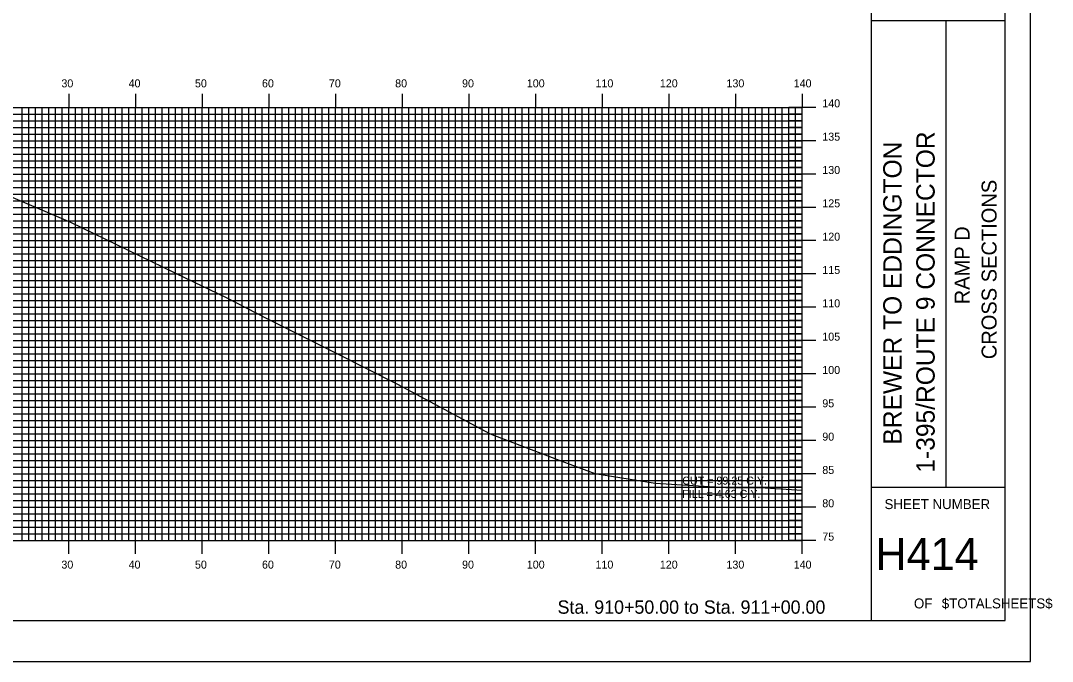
# Model space of a CAD drawing. Extents: x 859471 to 859814, y 364765 to 364985.
# Drawn here: x 859659.7 to 859814.4, y 364765.2 to 364861.3 of the extents above; entities that cross this region are included whole.
import ezdxf

# ---------------------------------------------------------------- set-up
doc = ezdxf.new("R2010")
doc.units = 0
for name, color, linetype in [('BORDER', 7, 'Continuous'), ('D_Text_Standard', 7, 'Continuous'), ('H_V ANNOTATION', 7, 'Continuous'), ('MAJOR', 7, 'Continuous'), ('MINOR', 7, 'Continuous'), ('PLOT BOUNDARY', 7, 'Continuous'), ('S_Roadway_Centerline', 7, 'Continuous')]:
    doc.layers.add(name, color=color, linetype=linetype)

msp = doc.modelspace()

# ---------------------------------------------------------------- linework, layer by layer
at = {"layer": 'BORDER'}
for p, q in [((859787.27, 364771.3), (859787.27, 364981.3)), ((859787.27, 364861.31), (859807.27, 364861.31)), ((859798.46, 364791.31), (859798.46, 364861.31)), ((859787.27, 364791.31), (859807.27, 364791.31))]:
    msp.add_line(p, q, dxfattribs=at)
msp.add_lwpolyline([(859487.27, 364771.3), (859807.27, 364771.3), (859807.27, 364981.3), (859487.27, 364981.3)], close=True, dxfattribs=at)
at = {"layer": 'MAJOR'}
for p, q in [((859666.87, 364850.31), (859666.87, 364848.3)), ((859676.87, 364850.31), (859676.87, 364848.3)), ((859686.87, 364850.31), (859686.87, 364848.3)), ((859696.87, 364850.31), (859696.87, 364848.3)), ((859706.87, 364850.31), (859706.87, 364848.3)), ((859716.87, 364850.31), (859716.87, 364848.3)), ((859726.87, 364850.31), (859726.87, 364848.3)), ((859736.87, 364850.31), (859736.87, 364848.3)), ((859746.87, 364850.31), (859746.87, 364848.3)), ((859756.87, 364850.31), (859756.87, 364848.3)), ((859766.87, 364850.31), (859766.87, 364848.3)), ((859776.87, 364850.31), (859776.87, 364848.3)), ((859496.87, 364848.3), (859776.87, 364848.3)), ((859496.87, 364848.3), (859776.87, 364848.3)), ((859666.87, 364783.3), (859666.87, 364848.3)), ((859676.87, 364783.3), (859676.87, 364848.3)), ((859686.87, 364783.3), (859686.87, 364848.3)), ((859696.87, 364783.3), (859696.87, 364848.3)), ((859706.87, 364783.3), (859706.87, 364848.3)), ((859716.87, 364783.3), (859716.87, 364848.3)), ((859726.87, 364783.3), (859726.87, 364848.3)), ((859736.87, 364783.3), (859736.87, 364848.3)), ((859746.87, 364783.3), (859746.87, 364848.3)), ((859756.87, 364783.3), (859756.87, 364848.3)), ((859766.87, 364783.3), (859766.87, 364848.3)), ((859778.88, 364848.3), (859774.87, 364848.3)), ((859776.87, 364783.3), (859776.87, 364848.3)), ((859776.87, 364783.3), (859776.87, 364848.3)), ((859496.87, 364843.3), (859776.87, 364843.3)), ((859778.88, 364843.3), (859774.87, 364843.3)), ((859496.87, 364838.3), (859776.87, 364838.3)), ((859778.88, 364838.3), (859774.87, 364838.3)), ((859496.87, 364833.3), (859776.87, 364833.3)), ((859778.88, 364833.3), (859774.87, 364833.3)), ((859496.87, 364828.3), (859776.87, 364828.3)), ((859778.88, 364828.3), (859774.87, 364828.3)), ((859496.87, 364823.3), (859776.87, 364823.3)), ((859778.88, 364823.3), (859774.87, 364823.3)), ((859496.87, 364818.3), (859776.87, 364818.3)), ((859778.88, 364818.3), (859774.87, 364818.3)), ((859496.87, 364813.3), (859776.87, 364813.3)), ((859778.88, 364813.3), (859774.87, 364813.3)), ((859496.87, 364808.3), (859776.87, 364808.3)), ((859778.88, 364808.3), (859774.87, 364808.3)), ((859496.87, 364803.3), (859776.87, 364803.3)), ((859778.88, 364803.3), (859774.87, 364803.3)), ((859496.87, 364798.3), (859776.87, 364798.3)), ((859778.88, 364798.3), (859774.87, 364798.3)), ((859496.87, 364793.3), (859776.87, 364793.3)), ((859778.88, 364793.3), (859774.87, 364793.3)), ((859496.87, 364788.3), (859776.87, 364788.3)), ((859778.88, 364788.3), (859774.87, 364788.3)), ((859496.87, 364783.3), (859776.87, 364783.3)), ((859496.87, 364783.3), (859776.87, 364783.3)), ((859666.87, 364781.3), (859666.87, 364783.3)), ((859676.87, 364781.3), (859676.87, 364783.3)), ((859686.87, 364781.3), (859686.87, 364783.3)), ((859696.87, 364781.3), (859696.87, 364783.3)), ((859706.87, 364781.3), (859706.87, 364783.3)), ((859716.87, 364781.3), (859716.87, 364783.3)), ((859726.87, 364781.3), (859726.87, 364783.3)), ((859736.87, 364781.3), (859736.87, 364783.3)), ((859746.87, 364781.3), (859746.87, 364783.3)), ((859756.87, 364781.3), (859756.87, 364783.3)), ((859766.87, 364781.3), (859766.87, 364783.3)), ((859778.88, 364783.3), (859774.87, 364783.3)), ((859776.87, 364781.3), (859776.87, 364783.3))]:
    msp.add_line(p, q, dxfattribs=at)
at = {"layer": 'MINOR'}
for p, q in [((859496.87, 364847.3), (859776.87, 364847.3)), ((859659.87, 364783.3), (859659.87, 364848.3)), ((859660.87, 364783.3), (859660.87, 364848.3)), ((859661.87, 364783.3), (859661.87, 364848.3)), ((859662.87, 364783.3), (859662.87, 364848.3)), ((859663.87, 364783.3), (859663.87, 364848.3)), ((859664.87, 364783.3), (859664.87, 364848.3)), ((859665.87, 364783.3), (859665.87, 364848.3)), ((859667.87, 364783.3), (859667.87, 364848.3)), ((859668.87, 364783.3), (859668.87, 364848.3)), ((859669.87, 364783.3), (859669.87, 364848.3)), ((859670.87, 364783.3), (859670.87, 364848.3)), ((859671.87, 364783.3), (859671.87, 364848.3)), ((859672.87, 364783.3), (859672.87, 364848.3)), ((859673.87, 364783.3), (859673.87, 364848.3)), ((859674.87, 364783.3), (859674.87, 364848.3)), ((859675.87, 364783.3), (859675.87, 364848.3)), ((859677.87, 364783.3), (859677.87, 364848.3)), ((859678.87, 364783.3), (859678.87, 364848.3)), ((859679.87, 364783.3), (859679.87, 364848.3)), ((859680.87, 364783.3), (859680.87, 364848.3)), ((859681.87, 364783.3), (859681.87, 364848.3)), ((859682.87, 364783.3), (859682.87, 364848.3)), ((859683.87, 364783.3), (859683.87, 364848.3)), ((859684.87, 364783.3), (859684.87, 364848.3)), ((859685.87, 364783.3), (859685.87, 364848.3)), ((859687.87, 364783.3), (859687.87, 364848.3)), ((859688.87, 364783.3), (859688.87, 364848.3)), ((859689.87, 364783.3), (859689.87, 364848.3)), ((859690.87, 364783.3), (859690.87, 364848.3)), ((859691.87, 364783.3), (859691.87, 364848.3)), ((859692.87, 364783.3), (859692.87, 364848.3)), ((859693.87, 364783.3), (859693.87, 364848.3)), ((859694.87, 364783.3), (859694.87, 364848.3)), ((859695.87, 364783.3), (859695.87, 364848.3)), ((859697.87, 364783.3), (859697.87, 364848.3)), ((859698.87, 364783.3), (859698.87, 364848.3)), ((859699.87, 364783.3), (859699.87, 364848.3)), ((859700.87, 364783.3), (859700.87, 364848.3)), ((859701.87, 364783.3), (859701.87, 364848.3)), ((859702.87, 364783.3), (859702.87, 364848.3)), ((859703.87, 364783.3), (859703.87, 364848.3)), ((859704.87, 364783.3), (859704.87, 364848.3)), ((859705.87, 364783.3), (859705.87, 364848.3)), ((859707.87, 364783.3), (859707.87, 364848.3)), ((859708.87, 364783.3), (859708.87, 364848.3)), ((859709.87, 364783.3), (859709.87, 364848.3)), ((859710.87, 364783.3), (859710.87, 364848.3)), ((859711.87, 364783.3), (859711.87, 364848.3)), ((859712.87, 364783.3), (859712.87, 364848.3)), ((859713.87, 364783.3), (859713.87, 364848.3)), ((859714.87, 364783.3), (859714.87, 364848.3)), ((859715.87, 364783.3), (859715.87, 364848.3)), ((859717.87, 364783.3), (859717.87, 364848.3)), ((859718.87, 364783.3), (859718.87, 364848.3)), ((859719.87, 364783.3), (859719.87, 364848.3)), ((859720.87, 364783.3), (859720.87, 364848.3)), ((859721.87, 364783.3), (859721.87, 364848.3)), ((859722.87, 364783.3), (859722.87, 364848.3)), ((859723.87, 364783.3), (859723.87, 364848.3)), ((859724.87, 364783.3), (859724.87, 364848.3)), ((859725.87, 364783.3), (859725.87, 364848.3)), ((859727.87, 364783.3), (859727.87, 364848.3)), ((859728.87, 364783.3), (859728.87, 364848.3)), ((859729.87, 364783.3), (859729.87, 364848.3)), ((859730.87, 364783.3), (859730.87, 364848.3)), ((859731.87, 364783.3), (859731.87, 364848.3)), ((859732.87, 364783.3), (859732.87, 364848.3)), ((859733.87, 364783.3), (859733.87, 364848.3)), ((859734.87, 364783.3), (859734.87, 364848.3)), ((859735.87, 364783.3), (859735.87, 364848.3)), ((859737.87, 364783.3), (859737.87, 364848.3)), ((859738.87, 364783.3), (859738.87, 364848.3)), ((859739.87, 364783.3), (859739.87, 364848.3)), ((859740.87, 364783.3), (859740.87, 364848.3)), ((859741.87, 364783.3), (859741.87, 364848.3)), ((859742.87, 364783.3), (859742.87, 364848.3)), ((859743.87, 364783.3), (859743.87, 364848.3)), ((859744.87, 364783.3), (859744.87, 364848.3)), ((859745.87, 364783.3), (859745.87, 364848.3)), ((859747.87, 364783.3), (859747.87, 364848.3)), ((859748.87, 364783.3), (859748.87, 364848.3)), ((859749.87, 364783.3), (859749.87, 364848.3)), ((859750.87, 364783.3), (859750.87, 364848.3)), ((859751.87, 364783.3), (859751.87, 364848.3)), ((859752.87, 364783.3), (859752.87, 364848.3)), ((859753.87, 364783.3), (859753.87, 364848.3)), ((859754.87, 364783.3), (859754.87, 364848.3)), ((859755.87, 364783.3), (859755.87, 364848.3)), ((859757.87, 364783.3), (859757.87, 364848.3)), ((859758.87, 364783.3), (859758.87, 364848.3)), ((859759.87, 364783.3), (859759.87, 364848.3)), ((859760.87, 364783.3), (859760.87, 364848.3)), ((859761.87, 364783.3), (859761.87, 364848.3)), ((859762.87, 364783.3), (859762.87, 364848.3)), ((859763.87, 364783.3), (859763.87, 364848.3)), ((859764.87, 364783.3), (859764.87, 364848.3)), ((859765.87, 364783.3), (859765.87, 364848.3)), ((859767.87, 364783.3), (859767.87, 364848.3)), ((859768.87, 364783.3), (859768.87, 364848.3)), ((859769.87, 364783.3), (859769.87, 364848.3)), ((859770.87, 364783.3), (859770.87, 364848.3)), ((859771.87, 364783.3), (859771.87, 364848.3)), ((859772.87, 364783.3), (859772.87, 364848.3)), ((859773.87, 364783.3), (859773.87, 364848.3)), ((859774.87, 364783.3), (859774.87, 364848.3)), ((859776.87, 364847.3), (859774.87, 364847.3)), ((859775.87, 364783.3), (859775.87, 364848.3)), ((859496.87, 364846.3), (859776.87, 364846.3)), ((859776.87, 364846.3), (859774.87, 364846.3)), ((859496.87, 364845.3), (859776.87, 364845.3)), ((859496.87, 364844.3), (859776.87, 364844.3)), ((859776.87, 364845.3), (859774.87, 364845.3)), ((859776.87, 364844.3), (859774.87, 364844.3)), ((859496.87, 364842.3), (859776.87, 364842.3)), ((859496.87, 364841.3), (859776.87, 364841.3)), ((859776.87, 364842.3), (859774.87, 364842.3)), ((859776.87, 364841.3), (859774.87, 364841.3)), ((859496.87, 364840.3), (859776.87, 364840.3)), ((859776.87, 364840.3), (859774.87, 364840.3)), ((859496.87, 364839.3), (859776.87, 364839.3)), ((859776.87, 364839.3), (859774.87, 364839.3)), ((859496.87, 364837.3), (859776.87, 364837.3)), ((859776.87, 364837.3), (859774.87, 364837.3)), ((859496.87, 364836.3), (859776.87, 364836.3)), ((859496.87, 364835.3), (859776.87, 364835.3)), ((859776.87, 364836.3), (859774.87, 364836.3)), ((859776.87, 364835.3), (859774.87, 364835.3)), ((859496.87, 364834.3), (859776.87, 364834.3)), ((859776.87, 364834.3), (859774.87, 364834.3)), ((859496.87, 364832.3), (859776.87, 364832.3)), ((859776.87, 364832.3), (859774.87, 364832.3)), ((859496.87, 364831.3), (859776.87, 364831.3)), ((859496.87, 364830.3), (859776.87, 364830.3)), ((859776.87, 364831.3), (859774.87, 364831.3)), ((859776.87, 364830.3), (859774.87, 364830.3)), ((859496.87, 364829.3), (859776.87, 364829.3)), ((859776.87, 364829.3), (859774.87, 364829.3)), ((859496.87, 364827.3), (859776.87, 364827.3)), ((859776.87, 364827.3), (859774.87, 364827.3)), ((859496.87, 364826.3), (859776.87, 364826.3)), ((859776.87, 364826.3), (859774.87, 364826.3)), ((859496.87, 364825.3), (859776.87, 364825.3)), ((859496.87, 364824.3), (859776.87, 364824.3)), ((859776.87, 364825.3), (859774.87, 364825.3)), ((859776.87, 364824.3), (859774.87, 364824.3)), ((859496.87, 364822.3), (859776.87, 364822.3)), ((859496.87, 364821.3), (859776.87, 364821.3)), ((859776.87, 364822.3), (859774.87, 364822.3)), ((859776.87, 364821.3), (859774.87, 364821.3)), ((859496.87, 364820.3), (859776.87, 364820.3)), ((859776.87, 364820.3), (859774.87, 364820.3)), ((859496.87, 364819.3), (859776.87, 364819.3)), ((859776.87, 364819.3), (859774.87, 364819.3)), ((859496.87, 364817.3), (859776.87, 364817.3)), ((859496.87, 364816.3), (859776.87, 364816.3)), ((859776.87, 364817.3), (859774.87, 364817.3)), ((859776.87, 364816.3), (859774.87, 364816.3)), ((859496.87, 364815.3), (859776.87, 364815.3)), ((859776.87, 364815.3), (859774.87, 364815.3)), ((859496.87, 364814.3), (859776.87, 364814.3)), ((859776.87, 364814.3), (859774.87, 364814.3)), ((859496.87, 364812.3), (859776.87, 364812.3)), ((859776.87, 364812.3), (859774.87, 364812.3)), ((859496.87, 364811.3), (859776.87, 364811.3)), ((859496.87, 364810.3), (859776.87, 364810.3)), ((859776.87, 364811.3), (859774.87, 364811.3)), ((859776.87, 364810.3), (859774.87, 364810.3)), ((859496.87, 364809.3), (859776.87, 364809.3)), ((859776.87, 364809.3), (859774.87, 364809.3)), ((859496.87, 364807.3), (859776.87, 364807.3)), ((859776.87, 364807.3), (859774.87, 364807.3)), ((859496.87, 364806.3), (859776.87, 364806.3)), ((859776.87, 364806.3), (859774.87, 364806.3)), ((859496.87, 364805.3), (859776.87, 364805.3)), ((859496.87, 364804.3), (859776.87, 364804.3)), ((859776.87, 364805.3), (859774.87, 364805.3)), ((859776.87, 364804.3), (859774.87, 364804.3)), ((859496.87, 364802.3), (859776.87, 364802.3)), ((859496.87, 364801.3), (859776.87, 364801.3)), ((859776.87, 364802.3), (859774.87, 364802.3)), ((859776.87, 364801.3), (859774.87, 364801.3)), ((859496.87, 364800.3), (859776.87, 364800.3)), ((859496.87, 364799.3), (859776.87, 364799.3)), ((859776.87, 364800.3), (859774.87, 364800.3)), ((859776.87, 364799.3), (859774.87, 364799.3)), ((859496.87, 364797.3), (859776.87, 364797.3)), ((859496.87, 364796.3), (859776.87, 364796.3)), ((859776.87, 364797.3), (859774.87, 364797.3)), ((859776.87, 364796.3), (859774.87, 364796.3)), ((859496.87, 364795.3), (859776.87, 364795.3)), ((859776.87, 364795.3), (859774.87, 364795.3)), ((859496.87, 364794.3), (859776.87, 364794.3)), ((859776.87, 364794.3), (859774.87, 364794.3)), ((859496.87, 364792.3), (859776.87, 364792.3)), ((859776.87, 364792.3), (859774.87, 364792.3)), ((859496.87, 364791.3), (859776.87, 364791.3)), ((859496.87, 364790.3), (859776.87, 364790.3)), ((859776.87, 364791.3), (859774.87, 364791.3)), ((859776.87, 364790.3), (859774.87, 364790.3)), ((859496.87, 364789.3), (859776.87, 364789.3)), ((859776.87, 364789.3), (859774.87, 364789.3)), ((859496.87, 364787.3), (859776.87, 364787.3)), ((859776.87, 364787.3), (859774.87, 364787.3)), ((859496.87, 364786.3), (859776.87, 364786.3)), ((859496.87, 364785.3), (859776.87, 364785.3)), ((859776.87, 364786.3), (859774.87, 364786.3)), ((859776.87, 364785.3), (859774.87, 364785.3)), ((859496.87, 364784.3), (859776.87, 364784.3)), ((859776.87, 364784.3), (859774.87, 364784.3))]:
    msp.add_line(p, q, dxfattribs=at)
at = {"layer": 'PLOT BOUNDARY'}
msp.add_lwpolyline([(859471.09, 364765.18), (859811.09, 364765.18), (859811.09, 364985.18), (859471.09, 364985.18)], close=True, dxfattribs=at)
at = {"layer": 'S_Roadway_Centerline'}
msp.add_lwpolyline([(859658.14, 364834.91), (859667.12, 364831.06), (859684.44, 364822.68), (859690.37, 364819.81), (859696.68, 364816.55), (859706.98, 364811.41), (859716.16, 364806.75), (859730.06, 364799.32), (859740.03, 364795.52), (859745.77, 364793.38), (859754.79, 364791.9), (859765.39, 364791.27), (859771.29, 364791.21), (859776.87, 364790.87)], dxfattribs=at)

# ---------------------------------------------------------------- texts
at = {"layer": 'BORDER'}
for s, height, p in [('1-395/ROUTE 9 CONNECTOR', 2.7557, (859796.72, 364793.5)), ('BREWER TO EDDINGTON', 2.7557, (859791.76, 364797.71)), ('CROSS SECTIONS', 2.25, (859806.01, 364810.52)), ('RAMP D', 2.25, (859801.96, 364818.75))]:
    msp.add_text(s, height=height, rotation=90, dxfattribs=at).set_placement(p)
for s, height, p in [('SHEET NUMBER', 1.4905, (859789.2, 364788.03)), ('H414', 4.839, (859787.85, 364778.87)), ('OF', 1.491, (859793.61, 364773.13)), ('$TOTALSHEETS$', 1.4905, (859797.79, 364773.13))]:
    msp.add_text(s, height=height, dxfattribs=at).set_placement(p)
at = {"layer": 'D_Text_Standard'}
for s, p in [('CUT = 99.25 C.Y.', (859758.87, 364791.7)), ('FILL = 4.63 C.Y.', (859758.87, 364789.71))]:
    msp.add_text(s, height=1.2, dxfattribs=at).set_placement(p)
at = {"layer": 'H_V ANNOTATION'}
for s, height, p in [('30', 1.2, (859665.77, 364851.3)), ('40', 1.2, (859675.85, 364851.3)), ('50', 1.2, (859685.8, 364851.3)), ('60', 1.2, (859695.85, 364851.3)), ('70', 1.2, (859705.88, 364851.3)), ('80', 1.2, (859715.82, 364851.3)), ('90', 1.2, (859725.85, 364851.3)), ('100', 1.2, (859735.56, 364851.3)), ('110', 1.2, (859745.86, 364851.3)), ('120', 1.2, (859755.51, 364851.3)), ('130', 1.2, (859765.5, 364851.3)), ('140', 1.2, (859775.58, 364851.3)), ('140', 1.2, (859779.87, 364848.3)), ('135', 1.2, (859779.87, 364843.3)), ('130', 1.2, (859779.87, 364838.3)), ('125', 1.2, (859779.87, 364833.3)), ('120', 1.2, (859779.87, 364828.3)), ('115', 1.2, (859779.87, 364823.3)), ('110', 1.2, (859779.87, 364818.3)), ('105', 1.2, (859779.87, 364813.3)), ('100', 1.2, (859779.87, 364808.3)), ('95', 1.2, (859779.87, 364803.3)), ('90', 1.2, (859779.87, 364798.3)), ('85', 1.2, (859779.87, 364793.3)), ('80', 1.2, (859779.87, 364788.3)), ('75', 1.2, (859779.87, 364783.3)), ('30', 1.2, (859665.77, 364779.1)), ('40', 1.2, (859675.85, 364779.1)), ('50', 1.2, (859685.8, 364779.1)), ('60', 1.2, (859695.85, 364779.1)), ('70', 1.2, (859705.88, 364779.1)), ('80', 1.2, (859715.82, 364779.1)), ('90', 1.2, (859725.85, 364779.1)), ('100', 1.2, (859735.56, 364779.1)), ('110', 1.2, (859745.86, 364779.1)), ('120', 1.2, (859755.51, 364779.1)), ('130', 1.2, (859765.5, 364779.1)), ('140', 1.2, (859775.58, 364779.1)), ('Sta. 910+50.00 to Sta. 911+00.00', 2.0004, (859740.17, 364772.33))]:
    msp.add_text(s, height=height, dxfattribs=at).set_placement(p)

doc.saveas('drawing.dxf')
